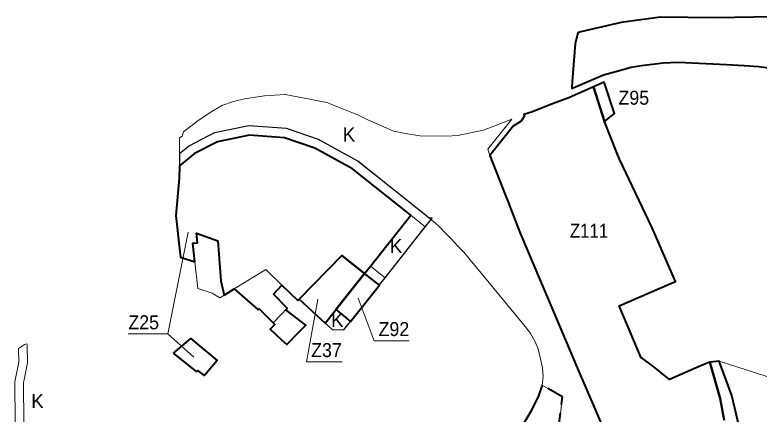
# Model space of a CAD drawing. Extents: x -650276 to -642489, y -1074311 to -1066658.
# Drawn here: x -650276 to -649001, y -1069852 to -1069167 of the extents above; entities that cross this region are included whole.
import ezdxf

# ---------------------------------------------------------------- set-up
doc = ezdxf.new("R2010")
doc.units = 0
doc.header["$LTSCALE"] = 9.6
doc.linetypes.add('MEDIUM_DASHED', pattern=[4.5, 3, -1.5])
for name, color, linetype, lineweight in [('42', 7, 'Continuous', 25), ('44', 7, 'Continuous', 40), ('45', 7, 'Continuous', 40), ('46', 7, 'Continuous', 13), ('47', 7, 'Continuous', 13), ('48', 7, 'Continuous', 13), ('61', 7, 'MEDIUM_DASHED', 40), ('63', 7, 'Continuous', 13)]:
    doc.layers.add(name, color=color, linetype=linetype, lineweight=lineweight)

msp = doc.modelspace()

# ---------------------------------------------------------------- linework, layer by layer
at = {"layer": '42'}
msp.add_lwpolyline([(-649641.978, -1069618.226), (-649572.972, -1069530.758), (-649561.91, -1069516.78), (-649561.17, -1069515.83), (-649566.951, -1069515.099), (-649688.625, -1069418.156), (-649755.971, -1069381.179), (-649810.846, -1069362.154), (-649875.434, -1069357.751), (-649934.363, -1069369.537), (-649945.397, -1069375.277), (-649977.239, -1069391.714), (-649994.329, -1069405.451), (-649994.293, -1069425.949), (-649994.53, -1069447.61), (-650000.59, -1069511.15), (-649992.59, -1069582.88), (-649967.81, -1069590.74), (-649971.38, -1069558.79), (-649963.43, -1069557.91), (-649965.26, -1069541.51), (-649928.48, -1069554.57), (-649924.62, -1069608.53), (-649923.17, -1069623.14), (-649918.35, -1069643.45), (-649917.38, -1069647.56), (-649900.64, -1069636.78), (-649877.82, -1069656.83), (-649859.96, -1069672.53), (-649859.17, -1069673.22), (-649857.49, -1069671.46), (-649833.94, -1069695.24), (-649833.94, -1069695.24), (-649819.98, -1069680.92), (-649809.47, -1069670.13), (-649833.38, -1069646.08), (-649818.71, -1069630.64), (-649791.3, -1069657.21), (-649788.91, -1069654.4), (-649744.517, -1069695.746), (-649744.517, -1069695.746), (-649732.52, -1069706.92), (-649712.64, -1069707.43), (-649708.322, -1069702.293), (-649701.211, -1069692.826), (-649651.773, -1069630.879), (-649651.846, -1069630.821), (-649651.846, -1069630.82)], close=True, dxfattribs=at)
at = {"layer": '44'}
for points in [[(-648781.015, -1069167.44), (-649076.02, -1069172.683), (-649169.781, -1069171.432), (-649237.512, -1069180.731), (-649277.021, -1069189.913), (-649306.455, -1069196.754), (-649311.633, -1069197.958), (-649316.47, -1069216.91), (-649321.32, -1069281.47), (-649322.09, -1069291.73), (-649322.22, -1069293.54), (-649319.72, -1069292.47), (-649267.5, -1069270.41), (-649242.5, -1069263.3), (-649220.18, -1069257.03), (-649202.63, -1069254.4), (-649165.62, -1069249.43), (-649139.63, -1069248.73), (-649056.95, -1069252.55), (-649026.955, -1069254.366), (-649001.3, -1069255.92), (-648968.49, -1069260.36)], [(-649032.928, -1069882.782), (-649048, -1069820), (-649069.4, -1069760.67), (-649085.41, -1069762.44), (-649068, -1069825.147), (-649060.897, -1069861.994)]]:
    msp.add_lwpolyline(points, dxfattribs=at)
msp.add_lwpolyline([(-649701.211, -1069692.826), (-649651.773, -1069630.879), (-649677.124, -1069610.681), (-649726.033, -1069672.415)], close=True, dxfattribs=at)
at = {"layer": '44', "lineweight": 13}
msp.add_lwpolyline([(-649600.782, -1069725.864), (-649660.57, -1069725.864), (-649688.04, -1069653.176)], dxfattribs=at)
at = {"layer": '45'}
msp.add_lwpolyline([(-649060.897, -1069861.994), (-649068, -1069825.147), (-649085.41, -1069762.44), (-649085.41, -1069762.44), (-649099.75, -1069768.575), (-649154.76, -1069792.11), (-649184.05, -1069768.45), (-649200.64, -1069756.53), (-649202.99, -1069754.99), (-649241.11, -1069665.9), (-649155.082, -1069629.097), (-649144.57, -1069624.6), (-649184.1, -1069532.2), (-649240.202, -1069414.528), (-649244.08, -1069404.753), (-649265.774, -1069350.068), (-649284.695, -1069291.033), (-649321.69, -1069307.61), (-649324.3, -1069308.59), (-649359.48, -1069321.82), (-649389.4, -1069333.35), (-649396.52, -1069336.09), (-649403.92, -1069338.26), (-649403.03, -1069340.66), (-649408.81, -1069349.89), (-649422.19, -1069357.99), (-649462.25, -1069408.32), (-649435.578, -1069476.772), (-649435.578, -1069476.772), (-649431.761, -1069486.57), (-649416.52, -1069525.68), (-649409.355, -1069544.517), (-649388.438, -1069594.296), (-649379.32, -1069615.71), (-649364.44, -1069650.55), (-649312.03, -1069773.33), (-649246.81, -1069926.27)], dxfattribs=at)
for points in [[(-649265.774, -1069350.068), (-649249.069, -1069336.66), (-649266.331, -1069282.804), (-649284.695, -1069291.033)], [(-649994.293, -1069425.949), (-649994.293, -1069425.949), (-649994.53, -1069447.61), (-650000.59, -1069511.15), (-649994.794, -1069563.119), (-649992.59, -1069582.88), (-649967.81, -1069590.74), (-649971.38, -1069558.79), (-649963.43, -1069557.91), (-649965.26, -1069541.51), (-649928.48, -1069554.57), (-649923.17, -1069623.14), (-649917.38, -1069647.56), (-649900.64, -1069636.78), (-649900.64, -1069636.78), (-649877.82, -1069656.83), (-649859.96, -1069672.53), (-649859.17, -1069673.22), (-649857.49, -1069671.46), (-649833.94, -1069695.24), (-649831.087, -1069698.045), (-649838.99, -1069706.15), (-649819.9, -1069723.61), (-649810.41, -1069732.28), (-649807.66, -1069729.46), (-649792.13, -1069713.65), (-649777.94, -1069699.2), (-649812.153, -1069672.884), (-649809.47, -1069670.13), (-649833.38, -1069646.08), (-649818.71, -1069630.64), (-649791.3, -1069657.21), (-649788.91, -1069654.4), (-649715.908, -1069579.804), (-649677.124, -1069610.681), (-649667.188, -1069598.14), (-649598.004, -1069510.814), (-649697.525, -1069431.522), (-649762.488, -1069395.854), (-649814.067, -1069377.972), (-649874.391, -1069373.859), (-649929.015, -1069384.784), (-649968.465, -1069405.189), (-649994.293, -1069425.949), (-649994.293, -1069425.949)], [(-649788.91, -1069654.4), (-649744.517, -1069695.746), (-649677.124, -1069610.681), (-649715.908, -1069579.804)], [(-649788.91, -1069654.4), (-649744.517, -1069695.746), (-649677.124, -1069610.681), (-649715.908, -1069579.804)], [(-650004.59, -1069747.27), (-649974.86, -1069721.96), (-649966.52, -1069728.87), (-649929.38, -1069759.65), (-649951.56, -1069785.42), (-649963, -1069776.7), (-649965, -1069778.7)], [(-650004.59, -1069747.27), (-649974.86, -1069721.96), (-649966.52, -1069728.87), (-649929.38, -1069759.65), (-649951.56, -1069785.42), (-649963, -1069776.7), (-649965, -1069778.7)]]:
    msp.add_lwpolyline(points, close=True, dxfattribs=at)
at = {"layer": '46'}
for points in [[(-650082.06, -1069714.05), (-650014.296, -1069714.05), (-649979.397, -1069539.747), (-650014.296, -1069714.05), (-649969.577, -1069753.88)], [(-649715.535, -1069761.925), (-649776.818, -1069761.925), (-649757.387, -1069654.603)], [(-649715.535, -1069761.925), (-649776.818, -1069761.925), (-649757.387, -1069654.603)], [(-650082.06, -1069714.05), (-650014.296, -1069714.05), (-650014.296, -1069714.05), (-649969.577, -1069753.88)]]:
    msp.add_lwpolyline(points, dxfattribs=at)
at = {"layer": '47'}
for points in [[(-649509.42, -1069372.61), (-649517.17, -1069374.3), (-649537.32, -1069375.23), (-649582.25, -1069374.51), (-649607.18, -1069370.92), (-649627.76, -1069366.8), (-649645.03, -1069358.8), (-649670.23, -1069347.9), (-649688.73, -1069338.7), (-649690.59, -1069337.98), (-649741.5, -1069317.74), (-649785.8, -1069308.94), (-649789, -1069308.31), (-649813.3, -1069303.66), (-649848.62, -1069305.95), (-649882.93, -1069311.1), (-649901.58, -1069316.01), (-649921.54, -1069323.03), (-649922.11, -1069323.35), (-649939.81, -1069333.47), (-649964.53, -1069350.02), (-649987.12, -1069368.03), (-649989.67, -1069375.36), (-649994.38, -1069378.33), (-649994.35, -1069394.43), (-649994.34, -1069398.8), (-649994.329, -1069405.451), (-649977.239, -1069391.714), (-649945.397, -1069375.277), (-649934.363, -1069369.537), (-649875.434, -1069357.751), (-649810.846, -1069362.154), (-649755.971, -1069381.179), (-649688.625, -1069418.156), (-649582.972, -1069502.334)], [(-649424.8, -1069346.14), (-649438.17, -1069351.27), (-649473.35, -1069364.76), (-649473.35, -1069364.76), (-649509.42, -1069372.61)], [(-649431.761, -1069486.57), (-649435.578, -1069476.772), (-649435.578, -1069476.772), (-649462.25, -1069408.32), (-649466.045, -1069397.373), (-649424.8, -1069346.14)], [(-649409.349, -1069544.532), (-649409.355, -1069544.517), (-649416.52, -1069525.68), (-649431.761, -1069486.57)], [(-649572.987, -1069530.746), (-649598.004, -1069510.814), (-649667.188, -1069598.14), (-649641.978, -1069618.226)], [(-649582.972, -1069502.334), (-649566.951, -1069515.099), (-649566.951, -1069515.099)], [(-649566.951, -1069515.099), (-649556.25, -1069523.62), (-649548.881, -1069530.963), (-649538.49, -1069541.54)], [(-649641.978, -1069618.226), (-649620.45, -1069590.75), (-649572.987, -1069530.746)], [(-649538.49, -1069541.54), (-649527.84, -1069552.16), (-649517.81, -1069563.27), (-649507.23, -1069573.85), (-649474.46, -1069613.59), (-649415.12, -1069685.26), (-649401.77, -1069701.47), (-649392.85, -1069713.53), (-649385.25, -1069726.48), (-649379.49, -1069740.04), (-649376.01, -1069754.58), (-649372.2, -1069772.58), (-649370.94, -1069787.45), (-649372.56, -1069802.33), (-649372.56, -1069802.33), (-649338, -1069822), (-649350.222, -1069920.873), (-649310.738, -1069929.342), (-649296.851, -1069931.092)], [(-649379.32, -1069615.71), (-649407.002, -1069550.701), (-649409.349, -1069544.532)], [(-649202.375, -1070030.469), (-649239.635, -1069943.094), (-649246.81, -1069926.27), (-649246.81, -1069926.27), (-649312.03, -1069773.33), (-649364.44, -1069650.55), (-649379.32, -1069615.71)], [(-649701.218, -1069692.82), (-649726.033, -1069672.415), (-649744.517, -1069695.746), (-649732.52, -1069706.92), (-649712.64, -1069707.43)], [(-649712.64, -1069707.43), (-649712.64, -1069707.43), (-649701.218, -1069692.82)], [(-650270.059, -1069739.232), (-650269.449, -1069762.714), (-650276.214, -1069796.532), (-650275.76, -1069865.474), (-650274.95, -1069865.62)], [(-650260.665, -1069868.303), (-650260.748, -1069867.327), (-650261.204, -1069797.969), (-650254.411, -1069764.006), (-650255.21, -1069733.253), (-650255.716, -1069731.162), (-650259.97, -1069732.29), (-650264.91, -1069735.69), (-650270.059, -1069739.232)]]:
    msp.add_lwpolyline(points, dxfattribs=at)
at = {"layer": '61'}
msp.add_lwpolyline([(-649372.56, -1069802.33), (-649379.19, -1069820.24), (-649391.86, -1069846.18), (-649406.53, -1069871.59), (-649417.234, -1069885.193), (-649350.222, -1069920.873), (-649338, -1069822)], close=True, dxfattribs=at)
at = {"layer": '63'}
for points in [[(-649266.331, -1069282.804), (-649284.695, -1069291.033), (-649321.69, -1069307.61), (-649359.48, -1069321.82), (-649396.52, -1069336.09), (-649403.92, -1069338.26), (-649403.03, -1069340.66), (-649408.81, -1069349.89), (-649422.19, -1069357.99), (-649462.25, -1069408.32), (-649435.578, -1069476.772), (-649431.761, -1069486.57), (-649416.52, -1069525.68), (-649329.217, -1069733.065), (-649329.217, -1069733.065)], [(-648914.48, -1069810.75), (-649069.4, -1069760.67), (-649085.41, -1069762.44), (-649154.76, -1069792.11), (-649184.05, -1069768.45), (-649200.64, -1069756.53), (-649202.99, -1069754.99), (-649241.11, -1069665.9), (-649144.57, -1069624.6), (-649184.1, -1069532.2), (-649240.202, -1069414.528), (-649265.774, -1069350.068), (-649249.069, -1069336.66), (-649266.331, -1069282.804)], [(-649563.306, -1069518.507), (-649561.17, -1069515.83), (-649566.951, -1069515.099), (-649582.972, -1069502.334), (-649690.441, -1069417.159), (-649755.971, -1069381.179), (-649810.846, -1069362.154), (-649875.434, -1069357.751), (-649934.363, -1069369.537), (-649977.239, -1069391.714), (-649994.329, -1069405.451)], [(-649994.329, -1069405.451), (-649994.26, -1069444.75), (-650000.59, -1069511.15), (-649998.5, -1069529.88), (-649992.59, -1069582.88), (-649967.81, -1069590.74), (-649962.71, -1069636.46), (-649938.2, -1069644.23), (-649924.8, -1069652.19), (-649917.38, -1069647.56), (-649907.07, -1069640.92), (-649900.64, -1069636.78), (-649846.38, -1069603.8), (-649818.71, -1069630.64)], [(-649700.42, -1069691.8), (-649658.13, -1069638.84), (-649620.45, -1069590.75), (-649563.306, -1069518.507)], [(-649818.71, -1069630.64), (-649818.71, -1069630.64), (-649791.3, -1069657.21), (-649788.91, -1069654.4), (-649732.52, -1069706.92), (-649712.64, -1069707.43), (-649700.42, -1069691.8)], [(-649329.217, -1069733.065), (-649246.81, -1069926.27), (-649246.81, -1069926.27)]]:
    msp.add_lwpolyline(points, dxfattribs=at)

# ---------------------------------------------------------------- texts
at = {"layer": '44', "width": 0.95}
for s, p in [('Z95', (-649242.024, -1069321.399)), ('Z92', (-649653.123, -1069717.932))]:
    msp.add_text(s, height=24, dxfattribs=at).set_placement(p)
at = {"layer": '46'}
for s, width, p in [('Z111', 0.9, (-649325.444, -1069549.35)), ('Z111', 0.9, (-649325.444, -1069549.35)), ('Z25', 0.95, (-650081.8, -1069706.363)), ('Z37', 0.95, (-649768.624, -1069753.993)), ('Z37', 0.95, (-649768.624, -1069753.993))]:
    msp.add_text(s, height=24, dxfattribs=dict(at, width=width)).set_placement(p)
at = {"layer": '48'}
for p in [(-649714.485, -1069384.456), (-649714.485, -1069384.456), (-649633.851, -1069575.59), (-649734.395, -1069702.217), (-650248.205, -1069841.413), (-650248.205, -1069841.413)]:
    msp.add_text('K', height=24, dxfattribs=at).set_placement(p)

doc.saveas('drawing.dxf')
